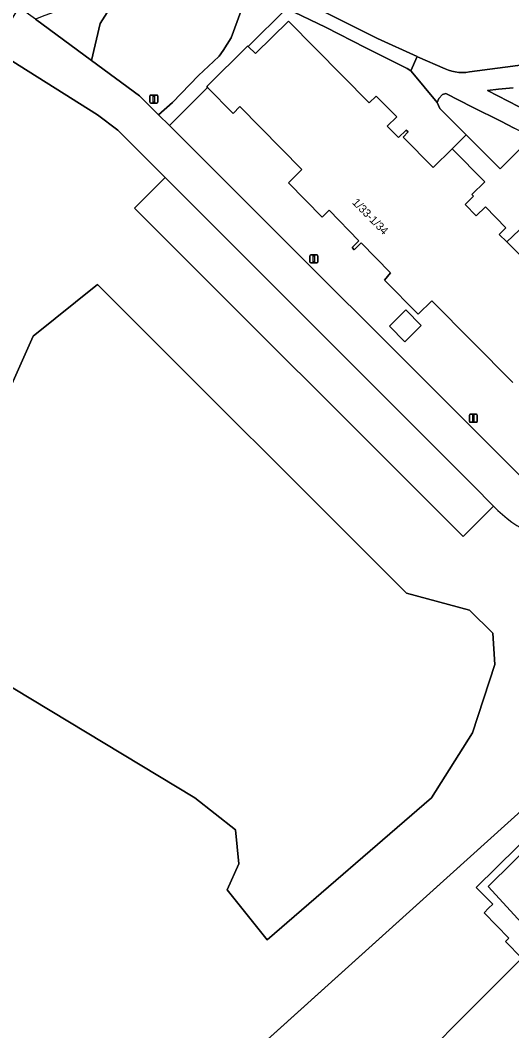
# Model space of a CAD drawing. Extents: x 162788 to 163838, y 385791 to 386523.
# Drawn here: x 162870 to 162931.3, y 385931.9 to 386058.1 of the extents above; entities that cross this region are included whole.
import ezdxf

# ---------------------------------------------------------------- set-up
doc = ezdxf.new("R2010")
doc.units = 0
for name, color, linetype in [('IMGEO_Erf', 7, 'Continuous'), ('IMGEO_Grasland_overig', 7, 'Continuous'), ('IMGEO_Groenvoorziening', 7, 'Continuous'), ('IMGEO_Hek', 7, 'Continuous'), ('IMGEO_Lichtmast', 7, 'Continuous'), ('IMGEO_Loofbos', 7, 'Continuous'), ('IMGEO_Pand', 7, 'Continuous'), ('IMGEO_Pand_nummerreeks', 7, 'Continuous'), ('IMGEO_Parkeervlak_halfverhard', 7, 'Continuous'), ('IMGEO_Woonerf_gesloten', 7, 'Continuous'), ('IMGEO_Woonerf_open', 7, 'Continuous')]:
    doc.layers.add(name, color=color, linetype=linetype)

msp = doc.modelspace()

# ---------------------------------------------------------------- linework, layer by layer
at = {"layer": 'IMGEO_Erf'}
for points in [[(162906.64, 386059.76), (162914.56, 386055.81), (162919.49, 386053.55), (162919.57, 386053.52), (162923, 386052.02), (162923.41, 386051.85), (162923.83, 386051.71), (162924.27, 386051.62), (162924.71, 386051.56), (162925.15, 386051.54), (162925.6, 386051.56), (162926.04, 386051.62), (162933.01, 386052.57)], [(162931.46, 386012.86), (162921.35, 386023.04), (162919.63, 386021.37), (162915.41, 386025.64), (162916.2, 386026.52), (162912.52, 386030.27), (162911.63, 386029.39), (162911.39, 386029.7), (162912.23, 386030.53), (162908.52, 386034.36), (162907.67, 386033.47), (162903.43, 386037.77), (162905.11, 386039.44), (162897.39, 386047.31), (162896.54, 386046.45), (162893.34, 386049.69), (162888.58, 386044.93), (162933.53, 386000)], [(162936.11, 386035.52), (162930.69, 386030.4), (162937.49, 386023.54)], [(162975.87, 385971.76), (162962.58, 385986.48), (162961.58, 385985.54), (162961.71, 385985.4), (162954.04, 385977.77), (162952.52, 385979.29), (162945.32, 385972.22), (162946.01, 385971.54), (162947.5, 385970.08), (162926.89, 385949.75), (162928.94, 385947.68), (162928.43, 385947.18), (162927.86, 385946.61), (162930.93, 385943.42), (162930.55, 385943.02), (162932.57, 385940.93), (162894.88, 385903.13), (162917.15, 385880.93), (162957.72, 385920.28), (162954.26, 385923.85), (162986.21, 385955.41)]]:
    msp.add_lwpolyline(points, dxfattribs=at)
for points in [[(162918.7, 386051.78), (162918.26, 386052.07), (162913.09, 386054.65), (162908.08, 386057.22), (162903.18, 386059.54), (162898.43, 386054.79), (162899.33, 386053.91), (162903.43, 386057.97), (162913.53, 386047.77), (162914.39, 386048.61), (162916.96, 386046.01), (162915.78, 386044.86), (162917.19, 386043.45), (162918.15, 386044.34), (162918.4, 386044.13), (162917.77, 386043.48), (162921.52, 386039.7), (162923.88, 386042.04), (162925.62, 386043.77), (162922.32, 386047.08), (162922, 386047.82), (162918.76, 386051.74)], [(162920.01, 386019.97), (162917.96, 386017.93), (162916.04, 386019.86), (162918.1, 386021.9)], [(162936.63, 385940.85), (162928.36, 385949.9), (162958.88, 385980.01), (162967.35, 385971.15), (162964.37, 385968.21)]]:
    msp.add_lwpolyline(points, close=True, dxfattribs=at)
at = {"layer": 'IMGEO_Grasland_overig'}
msp.add_lwpolyline([(162918.16, 385986.52), (162879.63, 386025.07), (162871.57, 386018.63), (162855.62, 385982.78), (162891.77, 385960.95), (162896.83, 385956.99), (162897.24, 385952.74), (162895.78, 385949.48), (162900.79, 385943.25), (162921.28, 385960.95), (162926.4, 385969.1), (162929.2, 385977.6), (162928.96, 385981.55), (162926.05, 385984.41)], close=True, dxfattribs=at)
msp.add_lwpolyline([(162894.88, 385903.13), (162932.57, 385940.93), (162930.55, 385943.02), (162930.93, 385943.42), (162927.86, 385946.61), (162928.43, 385947.18), (162928.94, 385947.68), (162926.89, 385949.75), (162947.5, 385970.08), (162946.01, 385971.54), (162943.62, 385969.38), (162933.35, 385960.12), (162894.46, 385925.05)], dxfattribs=at)
at = {"layer": 'IMGEO_Groenvoorziening'}
for points in [[(162889.98, 386073.46), (162879.93, 386057.68), (162878.87, 386053.05), (162884.86, 386048.66), (162887.24, 386046.27), (162888.96, 386047.8), (162892.21, 386051.18), (162894.09, 386052.95), (162894.78, 386053.6), (162895.31, 386054.29), (162896.29, 386055.9), (162898.87, 386062.98)], [(162931.51, 386049.65), (162929.66, 386049.48), (162928.28, 386049.3), (162933.44, 386046.66)]]:
    msp.add_lwpolyline(points, dxfattribs=at)
msp.add_lwpolyline([(162922, 386047.82), (162922.32, 386047.08), (162925.62, 386043.77), (162929.86, 386039.51), (162930.43, 386040.12), (162933.97, 386043.63), (162933.59, 386043.74), (162933.3, 386043.83), (162933.02, 386043.94), (162932.74, 386044.05), (162932.1, 386044.35), (162931.63, 386044.59), (162929.94, 386045.49), (162926.41, 386047.23), (162923.07, 386048.93), (162922.67, 386048.81), (162922.21, 386048.3)], close=True, dxfattribs=at)
at = {"layer": 'IMGEO_Hek'}
msp.add_lwpolyline([(162960.5, 385984.6), (162933.35, 385960.12), (162858.79, 385892.9), (162856.26, 385890.62), (162855.6, 385890.02)], dxfattribs=at)
at = {"layer": 'IMGEO_Lichtmast'}
for p, q in [((162886.15, 386047.84), (162886.15, 386048.64)), ((162886.15, 386048.64), (162886.15, 386047.84)), ((162886.25, 386048.74), (162887.03, 386048.74)), ((162887.03, 386048.74), (162886.25, 386048.74)), ((162887.13, 386048.64), (162887.13, 386047.84)), ((162887.13, 386047.84), (162887.13, 386048.64)), ((162887.03, 386047.74), (162886.25, 386047.74)), ((162886.25, 386047.74), (162887.03, 386047.74)), ((162906.12, 386027.88), (162906.12, 386028.68)), ((162906.12, 386028.68), (162906.12, 386027.88)), ((162906.22, 386028.78), (162907.01, 386028.78)), ((162907.01, 386028.78), (162906.22, 386028.78)), ((162907.11, 386028.68), (162907.11, 386027.88)), ((162907.11, 386027.88), (162907.11, 386028.68)), ((162907.01, 386027.78), (162906.22, 386027.78)), ((162906.22, 386027.78), (162907.01, 386027.78)), ((162926.02, 386007.97), (162926.02, 386008.77)), ((162926.02, 386008.77), (162926.02, 386007.97)), ((162926.12, 386008.87), (162926.91, 386008.87)), ((162926.91, 386008.87), (162926.12, 386008.87)), ((162927.01, 386008.77), (162927.01, 386007.97)), ((162927.01, 386007.97), (162927.01, 386008.77)), ((162926.91, 386007.87), (162926.12, 386007.87)), ((162926.12, 386007.87), (162926.91, 386007.87))]:
    msp.add_line(p, q, dxfattribs=at)
for points in [[(162886.57, 386048.62), (162886.72, 386048.62), (162886.72, 386047.87), (162886.57, 386047.87), (162886.57, 386048.62)], [(162906.54, 386028.66), (162906.69, 386028.66), (162906.69, 386027.91), (162906.54, 386027.91), (162906.54, 386028.66)], [(162926.44, 386008.75), (162926.59, 386008.75), (162926.59, 386008), (162926.44, 386008), (162926.44, 386008.75)]]:
    msp.add_lwpolyline(points, dxfattribs=at)
for centre, start, end in [((162886.25, 386048.64), 90, 180), ((162886.25, 386048.64), 90, 180), ((162887.03, 386048.64), 0, 90), ((162887.03, 386048.64), 360, 90), ((162886.25, 386047.84), 180, 270), ((162886.25, 386047.84), 180, 270), ((162887.03, 386047.84), 270, 0), ((162887.03, 386047.84), 270, 0), ((162906.22, 386028.68), 90, 180), ((162906.22, 386028.68), 90, 180), ((162907.01, 386028.68), 0, 90), ((162907.01, 386028.68), 360, 90), ((162906.22, 386027.88), 180, 270), ((162906.22, 386027.88), 180, 270), ((162907.01, 386027.88), 270, 0), ((162907.01, 386027.88), 270, 0), ((162926.12, 386008.77), 90, 180), ((162926.12, 386008.77), 90, 180), ((162926.12, 386007.97), 180, 270), ((162926.12, 386007.97), 180, 270), ((162926.91, 386008.77), 0, 90), ((162926.91, 386008.77), 360, 90), ((162926.91, 386007.97), 270, 0), ((162926.91, 386007.97), 270, 0)]:
    msp.add_arc(centre, 0.1, start, end, dxfattribs=at)
at = {"layer": 'IMGEO_Loofbos'}
for points in [[(162929.05, 385997.41), (162925.23, 385993.59), (162884.23, 386034.61), (162888.05, 386038.43), (162882.14, 386044.34), (162879.62, 386046.27), (162866.74, 386054.36), (162866.6, 386054.45), (162833.36, 386000), (162823.22, 385983.39)], [(162799.91, 385939.85), (162800.2, 385940.21), (162855.27, 385891.58), (162854.65, 385890.88), (162855.13, 385890.45), (162855.6, 385890.02), (162855.6, 385890.02), (162856.26, 385890.62), (162856.67, 385890.99), (162858.79, 385892.9), (162872.11, 385904.91), (162874.36, 385906.94), (162894.46, 385925.05), (162933.35, 385960.12), (162943.62, 385969.38), (162946.01, 385971.54), (162945.32, 385972.22), (162952.52, 385979.29), (162954.04, 385977.77), (162961.71, 385985.4), (162961.58, 385985.54), (162962.58, 385986.48), (162959.63, 385989.75)]]:
    msp.add_lwpolyline(points, dxfattribs=at)
msp.add_lwpolyline([(162897.24, 385952.74), (162896.83, 385956.99), (162891.77, 385960.95), (162855.62, 385982.78), (162871.57, 386018.63), (162879.63, 386025.07), (162918.16, 385986.52), (162926.05, 385984.41), (162928.96, 385981.55), (162929.2, 385977.6), (162926.4, 385969.1), (162921.28, 385960.95), (162900.79, 385943.25), (162895.78, 385949.48)], close=True, dxfattribs=at)
msp.add_arc((162940.09, 386007.67), 15.08, 222.9134, 268.8929, dxfattribs=at)
at = {"layer": 'IMGEO_Pand'}
msp.add_lwpolyline([(162937.49, 386023.54), (162930.69, 386030.4), (162929.75, 386031.34), (162930.59, 386032.17), (162928.02, 386034.78), (162926.88, 386033.64), (162925.48, 386035.07), (162926.53, 386036.11), (162926.34, 386036.3), (162927.97, 386037.92), (162923.88, 386042.04), (162921.52, 386039.7), (162917.77, 386043.48), (162918.4, 386044.13), (162918.15, 386044.34), (162917.19, 386043.45), (162915.78, 386044.86), (162916.96, 386046.01), (162914.39, 386048.61), (162913.53, 386047.77), (162903.43, 386057.97), (162899.33, 386053.91), (162898.43, 386054.79), (162898.35, 386054.86), (162893.24, 386049.79), (162893.34, 386049.69), (162896.54, 386046.45), (162897.39, 386047.31), (162905.11, 386039.44), (162903.43, 386037.77), (162907.67, 386033.47), (162908.52, 386034.36), (162912.23, 386030.53), (162911.39, 386029.7), (162911.63, 386029.39), (162912.52, 386030.27), (162916.2, 386026.52), (162915.41, 386025.64), (162919.63, 386021.37), (162921.35, 386023.04), (162931.46, 386012.86)], dxfattribs=at)
for points in [[(162916.04, 386019.86), (162917.96, 386017.93), (162920.01, 386019.97), (162918.1, 386021.9)], [(162967.35, 385971.15), (162958.88, 385980.01), (162928.36, 385949.9), (162936.63, 385940.85), (162964.37, 385968.21)]]:
    msp.add_lwpolyline(points, close=True, dxfattribs=at)
at = {"layer": 'IMGEO_Parkeervlak_halfverhard'}
msp.add_lwpolyline([(162888.05, 386038.43), (162884.23, 386034.61), (162925.23, 385993.59), (162929.05, 385997.41), (162926.46, 386000)], close=True, dxfattribs=at)
at = {"layer": 'IMGEO_Woonerf_gesloten'}
for points in [[(162898.87, 386062.98), (162896.29, 386055.9), (162895.31, 386054.29), (162894.78, 386053.6), (162894.09, 386052.95), (162892.21, 386051.18), (162888.96, 386047.8), (162887.24, 386046.27), (162888.58, 386044.93), (162893.34, 386049.69), (162893.24, 386049.79), (162898.35, 386054.86), (162898.43, 386054.79), (162903.18, 386059.54), (162908.08, 386057.22), (162913.09, 386054.65), (162918.26, 386052.07), (162918.7, 386051.78), (162919.49, 386053.55), (162914.56, 386055.81), (162906.64, 386059.76)], [(162888.58, 386044.93), (162887.24, 386046.27), (162884.86, 386048.66), (162878.87, 386053.05), (162871.86, 386058.2), (162869.96, 386059.6), (162869.81, 386059.71), (162866.6, 386054.45), (162866.74, 386054.36), (162879.62, 386046.27), (162882.14, 386044.34), (162888.05, 386038.43), (162926.46, 386000), (162929.05, 385997.41)], [(162933.53, 386000), (162888.58, 386044.93)]]:
    msp.add_lwpolyline(points, dxfattribs=at)
msp.add_arc((162940.09, 386007.67), 15.08, 222.9134, 268.8929, dxfattribs=at)
at = {"layer": 'IMGEO_Woonerf_open'}
for points in [[(162937.97, 386116.9), (162924.21, 386109.41), (162912.34, 386102.94), (162906.04, 386099.77), (162899.07, 386092.64), (162895.33, 386089.16), (162877.37, 386060.3), (162874.79, 386059.32), (162873.05, 386058.66), (162871.86, 386058.2), (162878.87, 386053.05), (162879.93, 386057.68), (162889.98, 386073.46), (162896.91, 386085.21), (162904.91, 386093.86), (162908.42, 386096.88), (162925.79, 386106.48), (162939.45, 386114.03)], [(162933.01, 386052.57), (162926.04, 386051.62), (162925.6, 386051.56), (162925.15, 386051.54), (162924.71, 386051.56), (162924.27, 386051.62), (162923.83, 386051.71), (162923.41, 386051.85), (162923, 386052.02), (162919.57, 386053.52), (162919.49, 386053.55), (162918.7, 386051.78), (162918.76, 386051.74), (162922, 386047.82), (162922.21, 386048.3), (162922.67, 386048.81), (162923.07, 386048.93), (162926.41, 386047.23), (162929.94, 386045.49), (162931.63, 386044.59)], [(162933.44, 386046.66), (162928.28, 386049.3), (162929.66, 386049.48), (162931.51, 386049.65)], [(162933.97, 386043.63), (162930.43, 386040.12), (162929.86, 386039.51), (162925.62, 386043.77), (162923.88, 386042.04), (162927.97, 386037.92), (162926.34, 386036.3), (162926.53, 386036.11), (162925.48, 386035.07), (162926.88, 386033.64), (162928.02, 386034.78), (162930.59, 386032.17), (162929.75, 386031.34), (162930.69, 386030.4), (162936.11, 386035.52)]]:
    msp.add_lwpolyline(points, dxfattribs=at)

# ---------------------------------------------------------------- texts
at = {"layer": 'IMGEO_Pand_nummerreeks'}
msp.add_text('1/33-1/34', height=1, rotation=314.5587, dxfattribs=at).set_placement((162911.33, 386035.24))

doc.saveas('drawing.dxf')
